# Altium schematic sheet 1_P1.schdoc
size 307 x 218 mm; Symbol: Drawing-Symbol_A4; Device: Drawing-Symbol_A4; @Project Name: Silicon dev board; @Page Count: 1; @Update Date: 2025-08-02; @Create Date: 2025-07-23; @Schematic Name: Schematic1; @Page No: 1; @Page Name: P1; Company: EasyEDA.com; Version: V1.0; Page Size: A4; @Create Time: 13:02:08; @Update Time: 16:22:57; Width: 1170; Height: 825; Region Start: 1; X Region Count: 6; Y Region Count: 4; Blade Width: 10; Title Block Position: 3; @Board Name: Board1
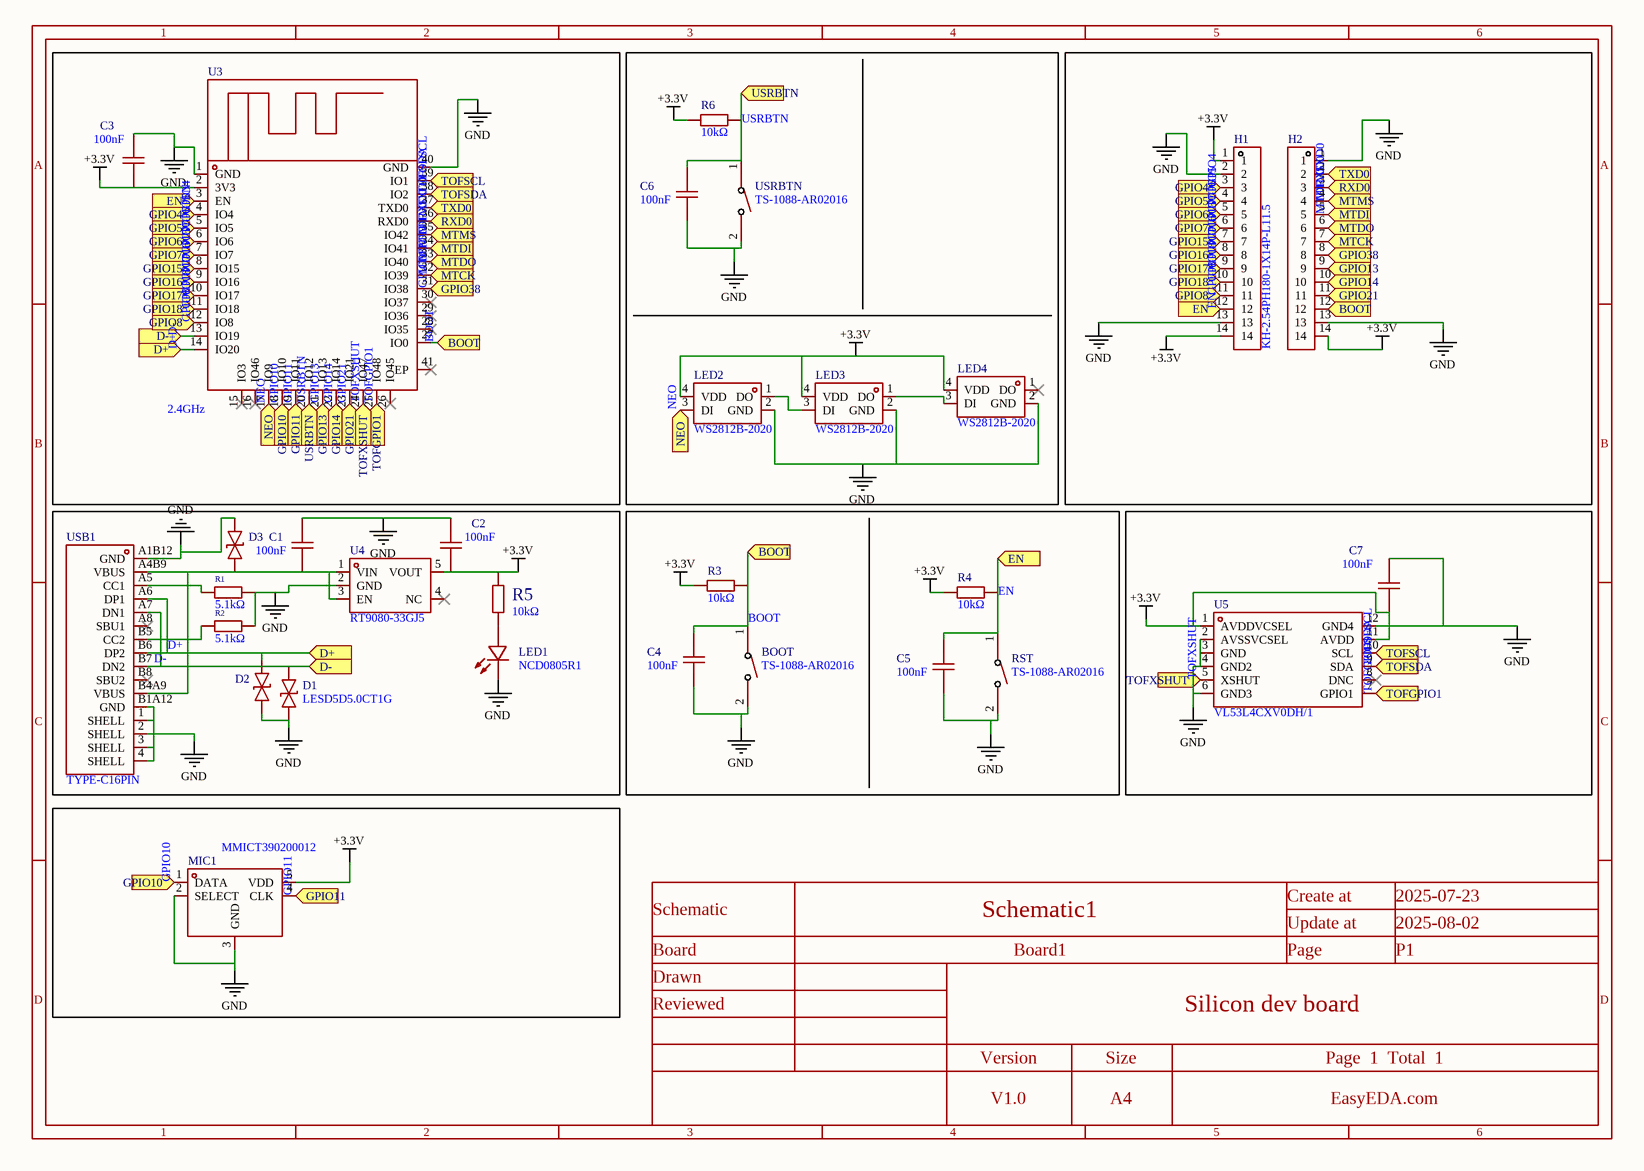
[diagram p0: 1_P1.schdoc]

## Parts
BOOT  TS-1088-AR02016  [SW-SMD_L3.9-W3.0-P4.45]
C1  100nF  [C0805]
C2  100nF  [C0805]
C3  100nF  [C0805]
C4  100nF  [C0805]
C5  100nF  [C0805]
C6  100nF  [C0805]
C7  100nF  [C0805]
D1  LESD5D5.0CT1G  [SOD-523_L1.2-W0.8-LS1.6-BI]
D2  LESD5D5.0CT1G  [SOD-523_L1.2-W0.8-LS1.6-BI]  (value not drawn)
D3  LESD5D5.0CT1G  [SOD-523_L1.2-W0.8-LS1.6-BI]  (value not drawn)
H1  KH-2.54PH180-1X14P-L11.5  [HDR-TH_14P-P2.54-V-M]
H2  KH-2.54PH180-1X14P-L11.5  [HDR-TH_14P-P2.54-V-M]  (value not drawn)
LED1  NCD0805R1  [LED0805-R-RD]
LED2  WS2812B-2020  [LED-SMD_4P-L2.0-W2.0-TL_WS2812B-2020]
LED3  WS2812B-2020  [LED-SMD_4P-L2.0-W2.0-TL_WS2812B-2020]
LED4  WS2812B-2020  [LED-SMD_4P-L2.0-W2.0-TL_WS2812B-2020]
MIC1  MMICT390200012  [MIC-SMD_5P-L3.5-W2.7-TL_MMICT390200012]
R1  5.1kΩ  [R0805]
R2  5.1kΩ  [R0805]
R3  10kΩ  [R0805]
R4  10kΩ  [R0805]
R5  10kΩ  [R0603]
R6  10kΩ  [R0805]
RST  TS-1088-AR02016  [SW-SMD_L3.9-W3.0-P4.45]
U3  2.4GHz  [WIFIM-SMD_ESP32-S3-WROOM-1-N8]
U4  RT9080-33GJ5  [TSOT-23-5_L2.9-W1.6-P0.95-LS2.8-BL]
U5  VL53L4CXV0DH/1  [OPTO-SMD_VL53L1CXV0FY-1]
USB1  TYPE-C16PIN  [USB-C-SMD_TYPE-C16PIN]
USRBTN  TS-1088-AR02016  [SW-SMD_L3.9-W3.0-P4.45]

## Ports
BOOT (in), D+ (in), D- (in), EN (in), GPIO4 (in), GPIO5 (in), GPIO6 (in), GPIO7 (in), GPIO8 (in), GPIO10 (in), GPIO11 (in), GPIO13 (in), GPIO14 (in), GPIO15 (in), GPIO16 (in), GPIO17 (in), GPIO18 (in), GPIO21 (in), GPIO38 (in), MTCK (in), MTDI (in), MTDO (in), MTMS (in), NEO (in), RXD0 (in), TOFGPIO1 (in), TOFSCL (in), TOFSDA (in), TOFXSHUT (in), TXD0 (in), USRBTN (in)

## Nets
+3.3V: C2.1 C3.1 C7.1 H1.1 H1.14 H2.14 LED2.4(VDD) LED3.4(VDD) LED4.4(VDD) MIC1.5(VDD) R3.1 R4.1 R5.2 R6.1 U3.2(3V3) U4.5(VOUT) U5.1(AVDDVCSEL) U5.11(AVDD)
GND: BOOT.2 C1.2 C2.2 C3.2 C4.1 C5.1 C6.1 C7.2 D1.1 D2.1 D3.2 H1.2 H1.13 H2.1 H2.13 LED1.2(-) LED2.2(GND) LED3.2(GND) LED4.2(GND) MIC1.2(SELECT) MIC1.3(GND) R1.2 R2.2 RST.2 U3.1(GND) U3.40(GND) U4.2(GND) U5.2(AVSSVCSEL) U5.3(GND) U5.4(GND2) U5.6(GND3) U5.12(GND4) USB1.1(SHELL) USB1.2(SHELL) USB1.3(SHELL) USB1.4(SHELL) USB1.A1B12(GND) USB1.B1A12(GND) USRBTN.2
BOOT: BOOT.1 C4.2 H2.12 R3.2 U3.27(IO0) ; port BOOT
D+: D2.2 U3.14(IO20) USB1.A6(DP1) USB1.B6(DP2) ; port D+
D-: D1.2 U3.13(IO19) USB1.A7(DN1) USB1.B7(DN2) ; port D-
EN: C5.2 H1.12 R4.2 RST.1 U3.3(EN) ; port EN
GPIO4: H1.3 U3.4(IO4) ; port GPIO4
GPIO5: H1.4 U3.5(IO5) ; port GPIO5
GPIO6: H1.5 U3.6(IO6) ; port GPIO6
GPIO7: H1.6 U3.7(IO7) ; port GPIO7
GPIO8: H1.11 U3.12(IO8) ; port GPIO8
GPIO10: MIC1.1(DATA) U3.18(IO10) ; port GPIO10
GPIO11: MIC1.4(CLK) U3.19(IO11) ; port GPIO11
GPIO13: H2.9 U3.21(IO13) ; port GPIO13
GPIO14: H2.10 U3.22(IO14) ; port GPIO14
GPIO15: H1.7 U3.8(IO15) ; port GPIO15
GPIO16: H1.8 U3.9(IO16) ; port GPIO16
GPIO17: H1.9 U3.10(IO17) ; port GPIO17
GPIO18: H1.10 U3.11(IO18) ; port GPIO18
GPIO21: H2.11 U3.23(IO21) ; port GPIO21
GPIO38: H2.8 U3.31(IO38) ; port GPIO38
MTCK: H2.7 U3.32(IO39) ; port MTCK
MTDI: H2.5 U3.34(IO41) ; port MTDI
MTDO: H2.6 U3.33(IO40) ; port MTDO
MTMS: H2.4 U3.35(IO42) ; port MTMS
NEO: LED2.3(DI) U3.17(IO9) ; port NEO
RXD0: H2.3 U3.36(RXD0) ; port RXD0
TOFGPIO1: U3.25(IO48) U5.7(GPIO1) ; port TOFGPIO1
TOFSCL: U3.39(IO1) U5.10(SCL) ; port TOFSCL
TOFSDA: U3.38(IO2) U5.9(SDA) ; port TOFSDA
TOFXSHUT: U3.24(IO47) U5.5(XSHUT) ; port TOFXSHUT
TXD0: H2.2 U3.37(TXD0) ; port TXD0
USRBTN: C6.2 R6.2 U3.20(IO12) USRBTN.1 ; port USRBTN
NetC1_1: C1.1 D3.1 U4.1(VIN) U4.3(EN) USB1.A4B9(VBUS) USB1.B4A9(VBUS)
NetLED1_1: LED1.1(+) R5.1
NetLED2_1: LED2.1(DO) LED3.3(DI)
NetLED3_1: LED3.1(DO) LED4.3(DI)
NetR1_1: R1.1 USB1.A5(CC1)
NetR2_1: R2.1 USB1.B5(CC2)

Not connected (* = marked no-connect by the designer): LED4 1(DO)*; U3 15(IO3)* 16(IO46)* 26(IO45)* 28(IO35)* 29(IO36)* 30(IO37)* 41(EP)*; U4 4(NC)*; U5 8(DNC)*; USB1 A8(SBU1)* B8(SBU2)*

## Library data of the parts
BOOT RST USRBTN = TS-1088-AR02016: Manufacturer: XUNPU(讯普); Add into BOM: yes; Circuit: SPST; Actuator Style: Round Button; Operating Force: 160gf; Switch Length: 4mm; Switch Width: 3mm; Switch Height: 2mm; Strike Gundam: 不带; Contact Current: 50mA; Voltage Rating (DC): 12V; Insulation Resistance: 100MΩ; Actuator/Cap Color: Black; Pin Style: SMDSplicing; Mechanical Life: 10万次
C1-C7 = C0805B104K500NT: Manufacturer: TORCH(火炬); Add into BOM: yes; Tolerance: ±10%; Voltage Rating: 50V; Temperature Coefficient: X7R
D1-D3 = LESD5D5.0CT1G: Manufacturer: LRC(乐山无线电); Add into BOM: yes; Polarity: Bidirectional; Reverse Stand-Off Voltage (Vrwm): 5V; Clamping Voltage: 18.6V; Peak Pulse Current (Ipp): 9.4A; Voltage - Breakdown: 5.6V; Type: ESD
H1 H2 = KH-2.54PH180-1X14P-L11.5: Manufacturer: kinghelm(金航标); Add into BOM: yes; Pin Structure: 1x14P; Pitch: 2.54mm; Circluar Pins/Square Pins: Policy; Current Rating: 3A
LED1 = NCD0805R1_C84256: Manufacturer: 国星光电; Symbol: FC-2012HRK-620D; Add into BOM: yes; Emitted Color: Red; Forward Voltage (VF): 1.6V~2.6V; Power Dissipation: 65mW; Forward Current: 20mA; Dominant Wavelength: 615nm~630nm; Diode Configuration: 独立二极管; Lens Color: 无色透明透镜; Luminous Intensity: 67mcd~195mcd; Viewing Angle: 130°
LED2-LED4 = WS2812B-2020: Manufacturer: worldsemi; Add into BOM: yes; Wavelength: 515.6nm；622.5nm；470.4nm
MIC1 = MMICT390200012: Manufacturer: TDK InvenSense(应美盛); Add into BOM: yes; Direction: Omni-directional; Voltage - Supply: 1.65V~3.63V; Current Consumption: 650uA; S/N Ratio: 64dB; Sensitivity: -32dB
R1 R2 = RMC08055.1K1%N: Manufacturer: Tyohm(幸亚电阻); Add into BOM: yes; Tolerance: ±1%; Power(Watts): 0.125W
R3 R4 R6 = PTFR0805B10K0N9: Manufacturer: RESI(开步睿思); Symbol: 0805W8F0000T5E; Add into BOM: yes; Tolerance: ±0.1%; Power(Watts): 130mW; Voltage-Supply(Max): 150V; Temperature Coefficient: ±10ppm/℃
R5 = 0603WAF1002T5E: Manufacturer: UNI-ROYAL(厚声); Add into BOM: yes; Tolerance: ±1%; Power(Watts): 100mW; Voltage-Supply(Max): 75V; Temperature Coefficient: ±100ppm/℃
U3 = ESP32-S3-WROOM-1-N8: Manufacturer: ESPRESSIF(乐鑫); Add into BOM: yes; Core Processor: ESP32-S3 Chip; Support Interface: I2C；GPIO；SPI；PWM；ADC；UART；USB；I2S
U4 = RT9080-33GJ5: Manufacturer: RICHTEK(立锜); Add into BOM: yes; Output Type: Fixed; Maximum Input Voltage: 5.5V; Output Voltage: 3.3V; Output Current: 600mA; Power Supply Rejection Ratio (PSRR): 75dB@(1kHz); Dropout Voltage: 530mV@(600mA); standby current: 4uA; Output Polarity: Positive electrode; Number of Outputs: 1
U5 = VL53L4CXV0DH/1: Manufacturer: ST(意法半导体); Add into BOM: yes; Voltage - Supply: 2.6V~3.5V; Linear Range: 0m~6m; Current - Supply: 21mA
USB1 = TYPE-C16PIN: Manufacturer: SHOU HAN(首韩); Add into BOM: yes; Connector Type: Type-C; Protocol Standard: USB 3.1; Gender: Female; Number of Contacts: 16P; Number of Ports: 1; Current Rating-Power: 3A; Voltage Rating: 30V; Connect-Disconnect Life: 10,000 Cycles; Detection color: Black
